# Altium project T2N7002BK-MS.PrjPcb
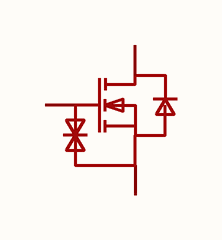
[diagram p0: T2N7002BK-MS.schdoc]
1 sheet, 1 parts. Net scope: global (net labels, ports and power ports of the same name join across sheets).

## Sheet T2N7002BK-MS.schdoc
size 127 x 101 mm

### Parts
Q?  t2n7002bk-ms  [SOT-23-3_L2.9-W1.3-P0.95-LS2.4-BR]  (value not drawn)

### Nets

Not connected (* = marked no-connect by the designer): Q? 1(G) 2(S) 3(D)

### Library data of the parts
Q? = t2n7002bk-ms: 类型:1个N沟道;漏源电压(Vdss):60V;连续漏极电流(Id):300mA;导通电阻(RDS(on)):2.2Ω@10V,300mA;耗散功率(Pd):350mW;阈值电压(Vgs(th)):1.6V;; Manufacturer: MSKSEMI(美森科); AddInBom: yes; ModelId: c62791f0466c4ae2a892c056b845b0ca; ModelName: SOT-23-3P_L2.9-W1.3-H1.0-LS2.4-P0.95; ModelTransform: 98.425,114.173,0,180,0,0,0.0005,-0.0005,0; Type: 1个N沟道; Drain to Source Voltage: 60V; Pd - Power Dissipation: 350mW; Gate Threshold Voltage (Vgs(th)@Id): 1.6V; Input Capacitance(Ciss@Vds): 38pF@30V; Reverse Transfer Capacitance (Crss@Vds): 12pF@30V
